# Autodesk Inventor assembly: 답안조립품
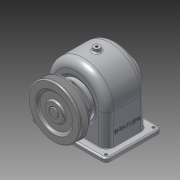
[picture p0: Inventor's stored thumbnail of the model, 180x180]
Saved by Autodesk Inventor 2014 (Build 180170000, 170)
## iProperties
Created: 2016-01
Part Number: 답안조립품
Document SubType Name: Assembly
Designer: user
Author: user
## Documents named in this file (16)
- C:\Users\user\Desktop\460106V1008\답안조립품.iam
- C:\Users\user\Desktop\460106V1008\본체.ipt
- C:\Users\user\Desktop\460106V1008\V-벨트풀리.ipt
- C:\Users\user\Desktop\460106V1008\뒤커버.ipt
- C:\Users\user\Desktop\460106V1008\멈춤나사 - M4x10.ipt
- C:\Users\user\Desktop\460106V1008\부시1.ipt
- C:\Users\user\Desktop\460106V1008\부시2.ipt
- C:\Users\user\Desktop\460106V1008\스퍼기어.ipt
- C:\Users\user\Desktop\460106V1008\앞커버.ipt
- C:\Users\user\Desktop\460106V1008\오일씰 28 40 8.ipt
- C:\Users\user\Desktop\460106V1008\축.ipt
- C:\Users\user\Desktop\460106V1008\키 - 5 x 5 x 18.ipt
- C:\Users\user\Desktop\460106V1008\키 - 6 x 6 x 22.ipt
- C:\Users\user\Desktop\460106V1008\베어링 6203.ipt
- C:\Users\user\Desktop\460106V1008\볼트 M3 x 8.ipt
- C:\Users\user\Desktop\460106V1008\볼트 M3 x 10.ipt
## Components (9 placed, 3 different names)
1. V-벨트풀리:1 — Insert:11, Mate:7
2. ISO 4762 M3 x 8:1 — Insert:13
3. ISO 4762 M3 x 10:1 — Insert:12
4. ISO 4762 M3 x 8:2
5. ISO 4762 M3 x 10:2
6. ISO 4762 M3 x 8:3
7. ISO 4762 M3 x 10:3
8. ISO 4762 M3 x 8:4
9. ISO 4762 M3 x 10:4
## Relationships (4: Insert 3, Mate 1)
- Insert:11: V-벨트풀리:1
- Mate:7: V-벨트풀리:1
- Insert:12: ISO 4762 M3 x 10:1
- Insert:13: ISO 4762 M3 x 8:1
